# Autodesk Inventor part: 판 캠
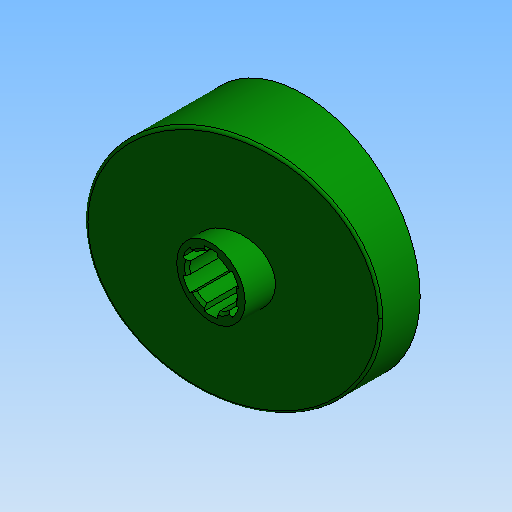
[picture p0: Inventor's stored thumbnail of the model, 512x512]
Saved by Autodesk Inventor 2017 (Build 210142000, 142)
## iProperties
Created: 2021-07
Part Number: 판 캠
Document SubType Name: 모델링
Designer: mdu
Material: 알루미늄 6061
Density: 2.71 g/cm^3
Mass: 235.299 g
Surface Area: 331.303 cm^2
Volume: 86.8264 cm^3
Appearance: 진녹색
변환 표준: STEP AP214IS
파일 이름: C:\Users\SeoGD\Desktop\?쒗뿕\??stp
전처리기: Build: 253, Release: 2010 SP1 - Date: Wed 07/29/2009
전송 단위: 밀리미터
불확실성: 0.01
Author: mdu
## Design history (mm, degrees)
node "작업 평면4"
sketch "스케치1"
  geometry: C1 r 44.5 at (0, 0); 1 further point
  constraints: 1 centre point, 1 coincident
  dimensions: "d25" = 89 diameter of C1
extrude "돌출1" new body sketch "스케치1" distance "d1" = 40; taper "d2" = 0 deg
sketch "스케치2"
  geometry: L1 (-44.5, 15)-(44.5, 38.847); L2 (-44.5, 0)-(-44.5, 40) reference; L3 (-44.5, 40)-(44.5, 40) reference; L4 (44.5, 0)-(44.5, 40) reference; 1 further point
  constraints: 2 end point, 2 point on line
  dimensions: "d26" = 15 distance of L2.start L1.start; "d27" = 75 deg angle of L1 L2
extrude "돌출2" cut sketch "스케치2" stored distance "d5" = 40; taper "d6" = 0 deg
node "작업 평면1"
sketch "스케치3"
  geometry: C1 r 13 at (0, 0); 1 further point
  constraints: 1 centre point, 1 coincident
  dimensions: "d9" = 26 diameter of C1
extrude "돌출3" join sketch "스케치3" distance "d10" = 38; taper "d11" = 0 deg
hole "구멍1" diameter "d14" = 18; stored, may be unused: countersink angle "d18" = 90 deg, drill point angle "d20" = 118 deg; dims "d12" = 10, "d13" = 10, "d15" = 6, "d16" = 4, "d17" = 2, "d19" = 8
feature "쉘2" dims "d29" = 5
sketch "스케치6"
  geometry: C1 r 17.5 at (0, 0); C2 r 14 at (0, 0) reference; 1 further point
  constraints: 1 centre point, 1 coincident
  dimensions: "d28" = 35 diameter of C1
extrude "돌출4" join sketch "스케치6" stored distance "d30" = 38; taper "d31" = 0 deg
fillet "모깎기1" dims "d32" = 3
chamfer "모따기1" distance "d21" = 1; stored, may be unused: second distance "d22" = 2, angle "d23" = 45 deg
sketch "스케치7"
  geometry: L1 (-12.374, 12.374)-(-27.931, 27.931); A1 r 39.5 centre (0, 0) between (-27.931, 27.931) and (0, 39.5) reference; 2 further points
  constraints: 2 end point, 2 point on circle, 1 point on line, 1 vertical alignment, 2 other
  dimensions: "d33" = 45 deg dimension on point (0, 0) L1.start A1.end
feature "리브1" sketch "스케치7" dims "d34" = 5, "d35" = 1, "d36" = 0
fillet "모깎기2" dims "d37" = 3
sketch "스케치8"
  geometry: L1 (2.5, 10.712)-(2.5, 8.646); L2 (-2.5, 10.712)-(-2.5, 8.646); A1 r 11 centre (0, 0) between (2.5, 10.712) and (-2.5, 10.712); A2 r 9 centre (0, 0) between (2.5, 8.646) and (-2.5, 8.646) reference; 1 further point
  constraints: 4 end point, 4 point on circle, 2 parallel, 1 centre point, 1 coincident, 1 vertical
  dimensions: "d41" = 22 diameter of A1; "d42" = 5 distance between parallel lines of L1 L2
extrude "돌출5" cut sketch "스케치8" stored distance "d43" = 38; taper "d44" = 0 deg
fillet "모깎기3" dims "d48" = 1
node "솔리드1"
node "솔리드 본체"
node "곡면 본체"
pattern_circular "원형 패턴1" dims angle "d39" = 360 deg
pattern_circular "원형 패턴2" dims angle "d46" = 360 deg
node "솔리드2"
